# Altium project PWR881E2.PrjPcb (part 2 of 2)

## Sheet PWR881E2.SchDoc: bq2597x and bq25890
size 431 x 279 mm; Date: Not shown in title block; ApprovedBy: Not shown in title block; CheckedBy: Not shown in title block; Author: Not shown in title block; CompanyName: Not shown in title block; Engineer: Not shown in title block; Organization: Not shown in title block; Address1: Not shown in title block; Address2: Not shown in title block; Address3: Not shown in title block; Address4: Not shown in title block; DocumentNumber: 1; Revision: Use project parameter SCH_Rev; SheetNumber: 3; SheetTotal: 4; PageSetup: Record=PageOptions¦CenterHorizontal=True¦CenterVertical=True¦PrintScale=1.00¦XCorrection=1.00¦YCorrection=1.00¦PrintKind=0¦BorderSize=5000000¦LeftOffset=0¦BottomOffset=0¦Orientation=2¦PaperLength=1000¦PaperWidth=1000¦Scale=100¦PaperSource=15¦PrintQuality=600¦MediaType=1¦DitherType=10¦PaperKind=Letter¦PrintScaleMode=1
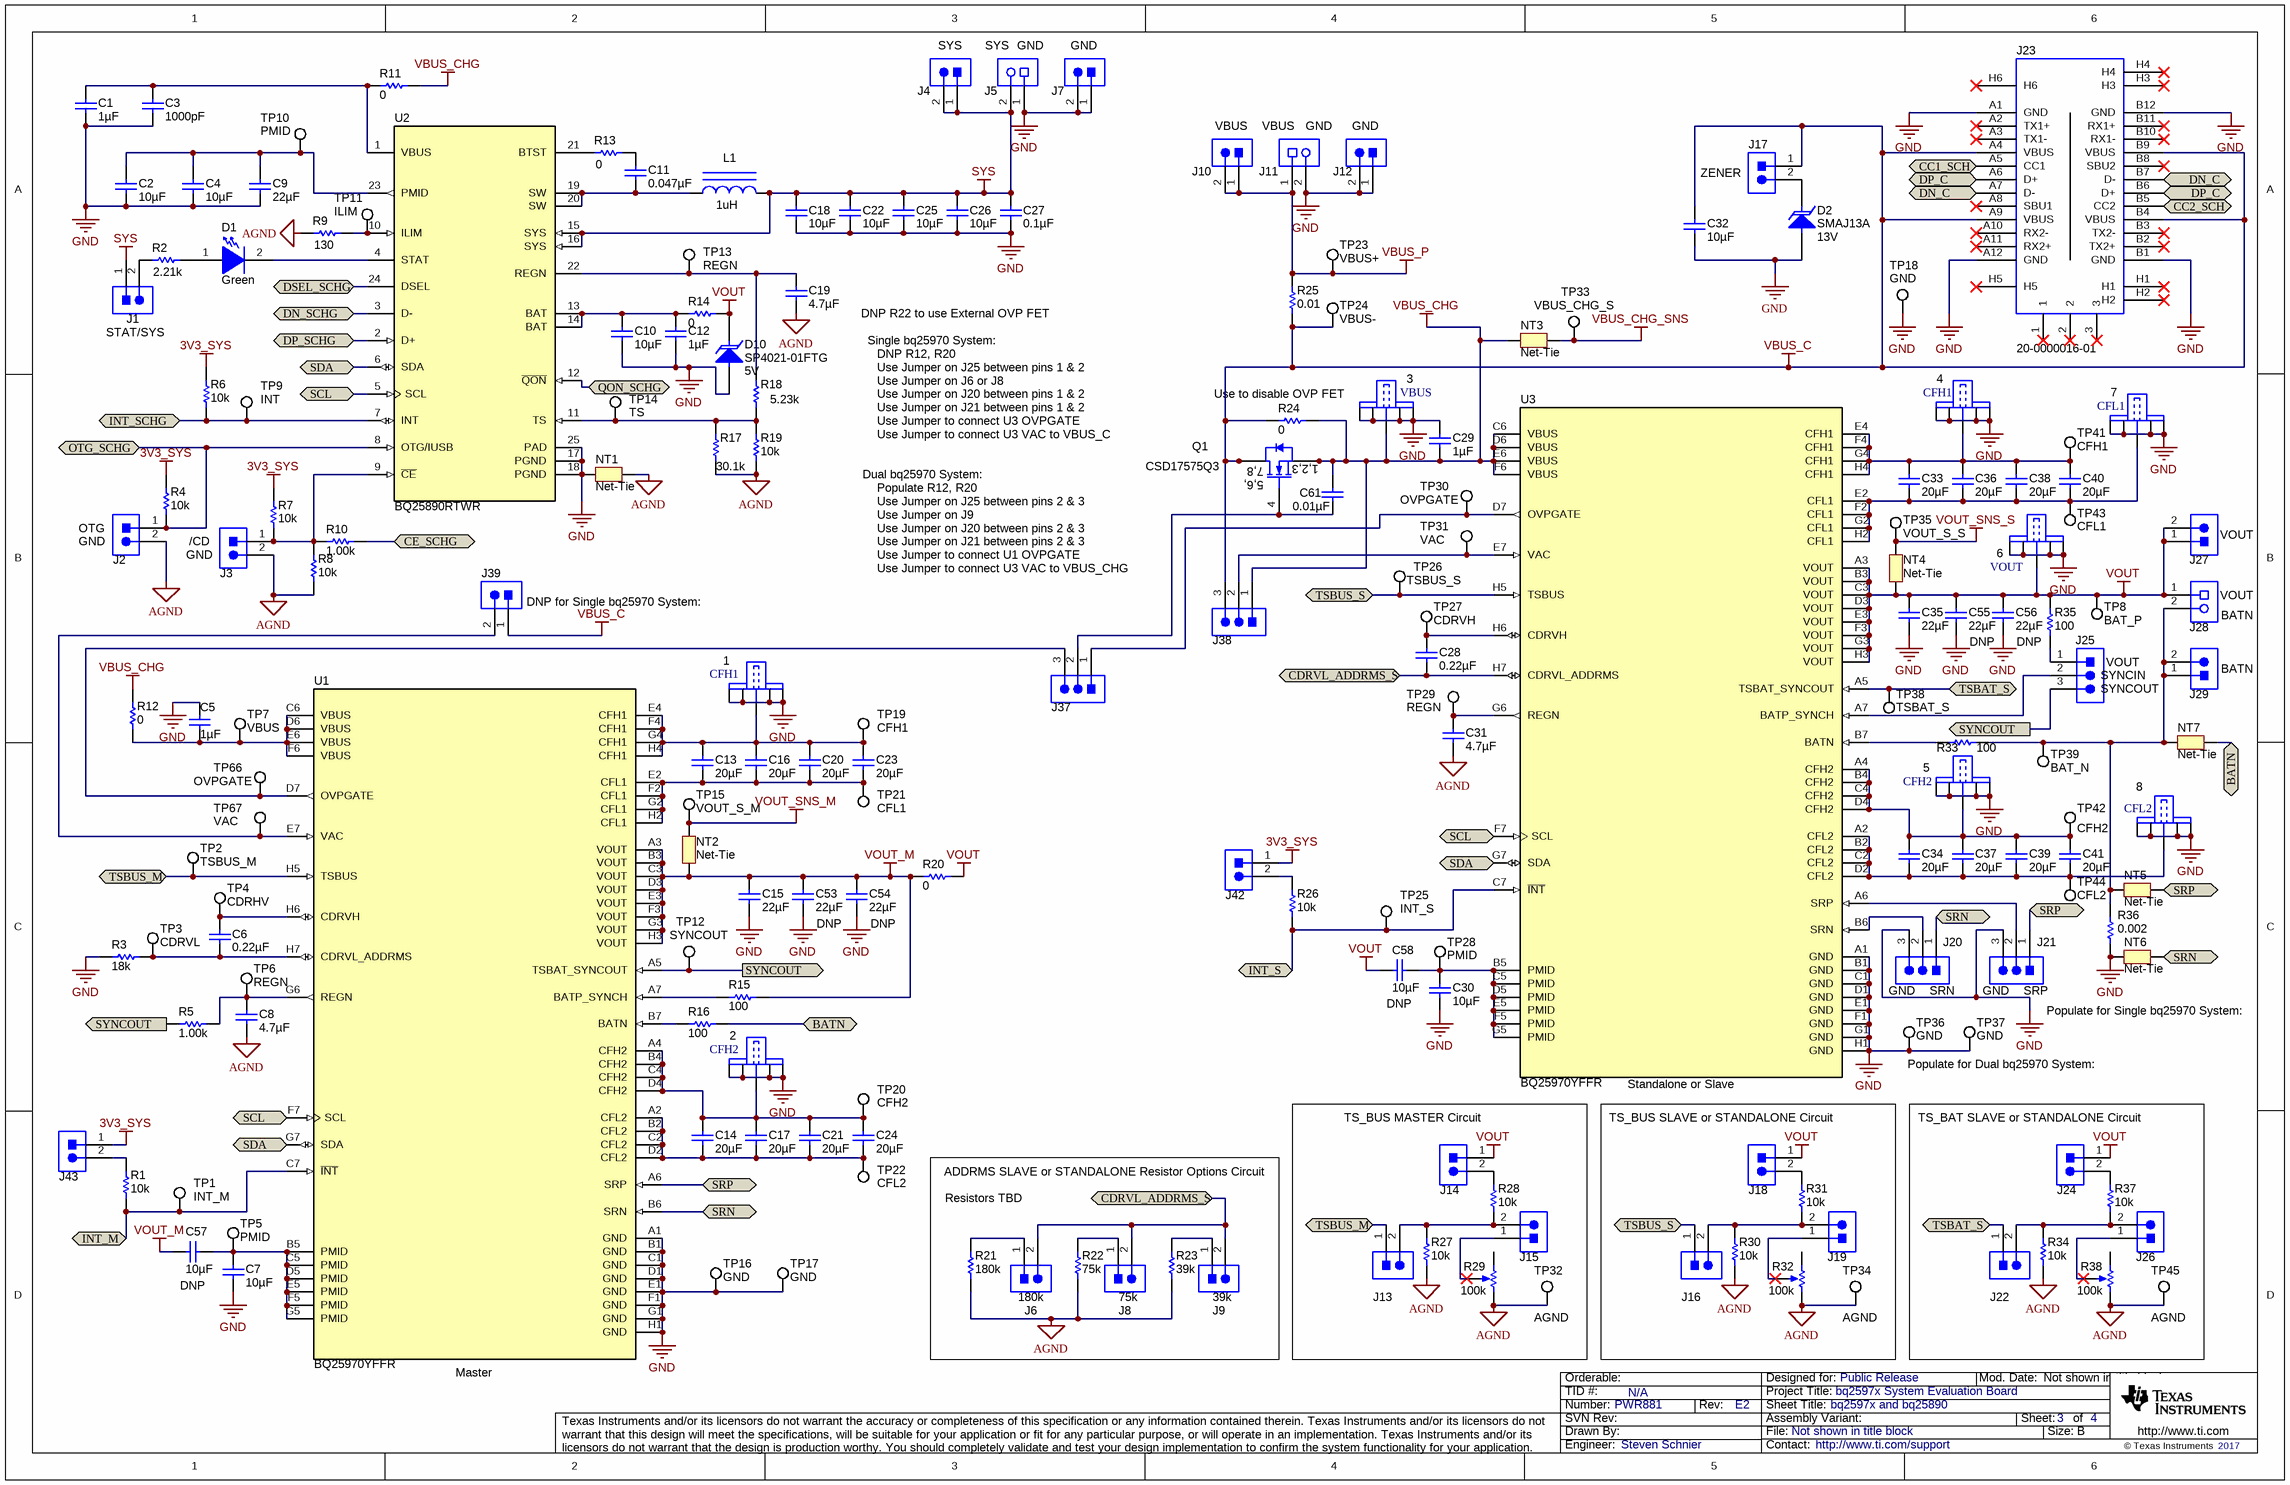
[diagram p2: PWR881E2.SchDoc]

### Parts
1  CFH1  [PROBE]
2  CFH2  [PROBE]
3  VBUS  [PROBE]
4  CFH1  [PROBE]
5  CFH2  [PROBE]
6  VOUT  [PROBE]
7  CFL1  [PROBE]
8  CFL2  [PROBE]
C1  ValueDisplayed: 1µF  [0805_HV]  (hidden comment: GRM219R71E105KA88D)
C2  ValueDisplayed: 10µF  [0603L]  (hidden comment: GRM188R61E106MA73D)
C3  ValueDisplayed: 1000pF  [0603L]  (hidden comment: GRM1885C1E102JA01D)
C4  ValueDisplayed: 10µF  [0603L]  (hidden comment: GRM188R61E106MA73D)
C5  ValueDisplayed: 1µF  [0603L]  (hidden comment: GRM188R61E105KA12D)
C6  ValueDisplayed: 0.22µF  [0402L]  (hidden comment: GRM155R71C224KA12D)
C7  ValueDisplayed: 10µF  [0603L]  (hidden comment: GRM188D71A106MA73D)
C8  ValueDisplayed: 4.7µF  [0402L]  (hidden comment: GRM155R61A475MEAAD)
C9  ValueDisplayed: 22µF  [0805_HV]  (hidden comment: GRM21BR61E226ME44L)
C10  ValueDisplayed: 10µF  [0805L]  (hidden comment: GRM21BR71A106KE51L)
C11  ValueDisplayed: 0.047µF  [0402L]  (hidden comment: GRM155R71E473KA88D)
C12  ValueDisplayed: 1µF  [0603L]  (hidden comment: C1608X7R1C105K080AC)
C13  ValueDisplayed: 20µF  [0704]  (hidden comment: GRMJN7R61C206ME05)
C14  ValueDisplayed: 20µF  [0704]  (hidden comment: GRMJN7R61C206ME05)
C15  ValueDisplayed: 22µF  [0603L]  (hidden comment: GRM188R61A226ME15D)
C16  ValueDisplayed: 20µF  [0704]  (hidden comment: GRMJN7R61C206ME05)
C17  ValueDisplayed: 20µF  [0704]  (hidden comment: GRMJN7R61C206ME05)
C18  ValueDisplayed: 10µF  [0805_HV]  (hidden comment: GRM21BR71A106KE51L)
C19  ValueDisplayed: 4.7µF  [0603L]  (hidden comment: GRM188R61C475KAAJ)
C20  ValueDisplayed: 20µF  [0704]  (hidden comment: GRMJN7R61C206ME05)
C21  ValueDisplayed: 20µF  [0704]  (hidden comment: GRMJN7R61C206ME05)
C22  ValueDisplayed: 10µF  [0805_HV]  (hidden comment: GRM21BR71A106KE51L)
C23  ValueDisplayed: 20µF  [0704]  (hidden comment: GRMJN7R61C206ME05)
C24  ValueDisplayed: 20µF  [0704]  (hidden comment: GRMJN7R61C206ME05)
C25  ValueDisplayed: 10µF  [0805_HV]  (hidden comment: GRM21BR71A106KE51L)
C26  ValueDisplayed: 10µF  [0805_HV]  (hidden comment: GRM21BR71A106KE51L)
C27  ValueDisplayed: 0.1µF  [0603L]  (hidden comment: C1608X7R1E104K080AA)
C28  ValueDisplayed: 0.22µF  [0402L]  (hidden comment: GRM155R71C224KA12D)
C29  ValueDisplayed: 1µF  [0603L]  (hidden comment: GRM188R61E105KA12D)
C30  ValueDisplayed: 10µF  [0603L]  (hidden comment: GRM188D71A106MA73D)
C31  ValueDisplayed: 4.7µF  [0402L]  (hidden comment: GRM155R61A475MEAAD)
C32  ValueDisplayed: 10µF  [0805_HV]  (hidden comment: C2012X5R1E106K125AB)
C33  ValueDisplayed: 20µF  [0704]  (hidden comment: GRMJN7R61C206ME05)
C34  ValueDisplayed: 20µF  [0704]  (hidden comment: GRMJN7R61C206ME05)
C35  ValueDisplayed: 22µF  [0603L]  (hidden comment: GRM188R61A226ME15D)
C36  ValueDisplayed: 20µF  [0704]  (hidden comment: GRMJN7R61C206ME05)
C37  ValueDisplayed: 20µF  [0704]  (hidden comment: GRMJN7R61C206ME05)
C38  ValueDisplayed: 20µF  [0704]  (hidden comment: GRMJN7R61C206ME05)
C39  ValueDisplayed: 20µF  [0704]  (hidden comment: GRMJN7R61C206ME05)
C40  ValueDisplayed: 20µF  [0704]  (hidden comment: GRMJN7R61C206ME05)
C41  ValueDisplayed: 20µF  [0704]  (hidden comment: GRMJN7R61C206ME05)
C53  ValueDisplayed: 22µF  [0603L]  (hidden comment: GRM188R61A226ME15D)
C54  ValueDisplayed: 22µF  [0603L]  (hidden comment: GRM188R61A226ME15D)
C55  ValueDisplayed: 22µF  [0603L]  (hidden comment: GRM188R61A226ME15D)
C56  ValueDisplayed: 22µF  [0603L]  (hidden comment: GRM188R61A226ME15D)
C57  ValueDisplayed: 10µF  [0603L]  (hidden comment: GRM188D71A106MA73D)
C58  ValueDisplayed: 10µF  [0603L]  (hidden comment: GRM188D71A106MA73D)
C61  ValueDisplayed: 0.01µF  [0603L]  (hidden comment: GRM188R71E103KA01D)
D1  value Green  [LED_LTST-C190]  (hidden comment: LTST-C190GKT)
D2  SMAJ13A  value 13V  [SMA]
D10  SP4021-01FTG  value 5V  [SOD-323]
J1  STAT/SYS  [CONN_PEC02SAAN]
J2  PEC02SAAN  [CONN_PEC02SAAN]  (value not drawn)
J3  PEC02SAAN  [CONN_PEC02SAAN]  (value not drawn)
J4  PEC02SAAN  [CONN_PEC02SAAN]  (value not drawn)
J5  1727010  [PhoenixConact_1727010]  (value not drawn)
J6  180k  [CONN_PEC02SAAN]
J7  PEC02SAAN  [CONN_PEC02SAAN]  (value not drawn)
J8  75k  [CONN_PEC02SAAN]
J9  39k  [CONN_PEC02SAAN]
J10  PEC02SAAN  [CONN_PEC02SAAN]  (value not drawn)
J11  1727010  [PhoenixConact_1727010]  (value not drawn)
J12  PEC02SAAN  [CONN_PEC02SAAN]  (value not drawn)
J13  PEC02SAAN  [CONN_PEC02SAAN]  (value not drawn)
J14  PEC02SAAN  [CONN_PEC02SAAN]  (value not drawn)
J15  PEC02SAAN  [CONN_PEC02SAAN]  (value not drawn)
J16  PEC02SAAN  [CONN_PEC02SAAN]  (value not drawn)
J17  PEC02SAAN  [CONN_PEC02SAAN]  (value not drawn)
J18  PEC02SAAN  [CONN_PEC02SAAN]  (value not drawn)
J19  PEC02SAAN  [CONN_PEC02SAAN]  (value not drawn)
J20  TSW-103-07-T-S  [Samtec_TSW-103-07-T-S]  (value not drawn)
J21  TSW-103-07-T-S  [Samtec_TSW-103-07-T-S]  (value not drawn)
J22  PEC02SAAN  [CONN_PEC02SAAN]  (value not drawn)
J23  20-0000016-01  [Lintes_20-0000016-01]
J24  PEC02SAAN  [CONN_PEC02SAAN]  (value not drawn)
J25  TSW-103-07-T-S  [Samtec_TSW-103-07-T-S]  (value not drawn)
J26  PEC02SAAN  [CONN_PEC02SAAN]  (value not drawn)
J27  PEC02SAAN  [CONN_PEC02SAAN]  (value not drawn)
J28  1727010  [PhoenixConact_1727010]  (value not drawn)
J29  PEC02SAAN  [CONN_PEC02SAAN]  (value not drawn)
J37  TSW-103-07-T-S  [Samtec_TSW-103-07-T-S]  (value not drawn)
J38  TSW-103-07-T-S  [Samtec_TSW-103-07-T-S]  (value not drawn)
J39  PEC02SAAN  [CONN_PEC02SAAN]  (value not drawn)
J42  PEC02SAAN  [CONN_PEC02SAAN]  (value not drawn)
J43  PEC02SAAN  [CONN_PEC02SAAN]  (value not drawn)
L1  value 1uH  [IHLP-2020BZ]  (hidden comment: IHLP2020BZER1R0M11)
NT1  Net-Tie  [Net-Tie_10milWide_30milLong]  (net tie, no BOM)
NT2  Net-Tie  [Net-Tie_10milWide_30milLong]  (net tie, no BOM)
NT3  Net-Tie  [Net-Tie_10milWide_30milLong]  (net tie, no BOM)
NT4  Net-Tie  [Net-Tie_10milWide_30milLong]  (net tie, no BOM)
NT5  Net-Tie  [Net-Tie_10milWide_30milLong]  (net tie, no BOM)
NT6  Net-Tie  [Net-Tie_10milWide_30milLong]  (net tie, no BOM)
NT7  Net-Tie  [Net-Tie_10milWide_30milLong]  (net tie, no BOM)
Q1  CSD17575Q3  [DQG0008A]
R1  ValueDisplayed: 10k  [0402L]  (hidden comment: CRCW040210K0JNED)
R2  ValueDisplayed: 2.21k  [0402L]  (hidden comment: CRCW04022K21FKED)
R3  ValueDisplayed: 18k  [0402L]  (hidden comment: CRCW040218K0JNED)
R4  ValueDisplayed: 10k  [0402L]  (hidden comment: CRCW040210K0JNED)
R5  ValueDisplayed: 1.00k  [0603L]  (hidden comment: RC0603FR-071KL)
R6  ValueDisplayed: 10k  [0402L]  (hidden comment: CRCW040210K0JNED)
R7  ValueDisplayed: 10k  [0402L]  (hidden comment: CRCW040210K0JNED)
R8  ValueDisplayed: 10k  [0402L]  (hidden comment: CRCW040210K0JNED)
R9  ValueDisplayed: 130  [0402L]  (hidden comment: CRCW0402130RFKED)
R10  ValueDisplayed: 1.00k  [0603L]  (hidden comment: RC0603FR-071KL)
R11  ValueDisplayed: 0  [2512L]  (hidden comment: CRCW25120000Z0EGHP)
R12  ValueDisplayed: 0  [2512L]  (hidden comment: CRCW25120000Z0EGHP)
R13  ValueDisplayed: 0  [0402L]  (hidden comment: CRCW04020000Z0ED)
R14  ValueDisplayed: 0  [5106]  (hidden comment: 5106)
R15  ValueDisplayed: 100  [0603L]  (hidden comment: CRCW0603100RJNEA)
R16  ValueDisplayed: 100  [0603L]  (hidden comment: CRCW0603100RJNEA)
R17  ValueDisplayed: 30.1k  [0402L]  (hidden comment: CRCW040230K1FKED)
R18  ValueDisplayed: 5.23k  [0402L]  (hidden comment: CRCW04025K23FKED)
R19  ValueDisplayed: 10k  [0402L]  (hidden comment: CRCW040210K0JNED)
R20  ValueDisplayed: 0  [2512L]  (hidden comment: CRCW25120000Z0EGHP)
R21  ValueDisplayed: 180k  [0402]  (hidden comment: CRCW0402180KJNED)
R22  ValueDisplayed: 75k  [0402]  (hidden comment: CRCW040275K0JNED)
R23  ValueDisplayed: 39k  [0402]  (hidden comment: CRCW040239K0JNED)
R24  ValueDisplayed: 0  [2512L]  (hidden comment: CRCW25120000Z0EGHP)
R25  ValueDisplayed: 0.01  [1206]  (hidden comment: WSLP1206R0100FEA)
R26  ValueDisplayed: 10k  [0402L]  (hidden comment: CRCW040210K0JNED)
R27  ValueDisplayed: 10k  [0402]  (hidden comment: CRCW040210K0JNED)
R28  ValueDisplayed: 10k  [0402]  (hidden comment: CRCW040210K0JNED)
R29  value 100k  [TRIM_3266W]  (hidden comment: 3266W-1-104LF)
R30  ValueDisplayed: 10k  [0402]  (hidden comment: CRCW040210K0JNED)
R31  ValueDisplayed: 10k  [0402]  (hidden comment: CRCW040210K0JNED)
R32  value 100k  [TRIM_3266W]  (hidden comment: 3266W-1-104LF)
R33  ValueDisplayed: 100  [0603L]  (hidden comment: CRCW0603100RJNEA)
R34  ValueDisplayed: 10k  [0402]  (hidden comment: CRCW040210K0JNED)
R35  ValueDisplayed: 100  [0603L]  (hidden comment: CRCW0603100RJNEA)
R36  ValueDisplayed: 0.002  [1206]  (hidden comment: CSNL1206FT2L00)
R37  ValueDisplayed: 10k  [0402]  (hidden comment: CRCW040210K0JNED)
R38  value 100k  [TRIM_3266W]  (hidden comment: 3266W-1-104LF)
TP1  INT_M  [Keystone5002]
TP2  TSBUS_M  [Keystone5012]
TP3  CDRVL  [Keystone5012]
TP4  CDRHV  [Keystone5012]
TP5  PMID  [Keystone5012]
TP6  REGN  [Keystone5012]
TP7  VBUS  [Keystone5012]
TP8  BAT_P  [Keystone5012]
TP9  INT  [Keystone5012]
TP10  PMID  [Keystone5012]
TP11  ILIM  [Keystone5012]
TP12  SYNCOUT  [Keystone5012]
TP13  REGN  [Keystone5012]
TP14  TS  [Keystone5012]
TP15  VOUT_S_M  [Keystone5012]
TP16  GND  [Keystone5012]
TP17  GND  [Keystone5012]
TP18  GND  [Keystone5012]
TP19  CFH1  [Keystone5012]
TP20  CFH2  [Keystone5012]
TP21  CFL1  [Keystone5012]
TP22  CFL2  [Keystone5012]
TP23  VBUS+  [Keystone5012]
TP24  VBUS-  [Keystone5012]
TP25  INT_S  [Keystone5002]
TP26  TSBUS_S  [Keystone5012]
TP27  CDRVH  [Keystone5012]
TP28  PMID  [Keystone5012]
TP29  REGN  [Keystone5012]
TP30  OVPGATE  [Keystone5012]
TP31  VAC  [Keystone5012]
TP32  AGND  [Keystone5012]
TP33  VBUS_CHG_S  [Keystone5012]
TP34  AGND  [Keystone5012]
TP35  VOUT_S_S  [Keystone5012]
TP36  GND  [Keystone5012]
TP37  GND  [Keystone5012]
TP38  TSBAT_S  [Keystone5012]
TP39  BAT_N  [Keystone5012]
TP41  CFH1  [Keystone5012]
TP42  CFH2  [Keystone5012]
TP43  CFL1  [Keystone5012]
TP44  CFL2  [Keystone5012]
TP45  AGND  [Keystone5012]
TP66  OVPGATE  [Keystone5012]
TP67  VAC  [Keystone5012]
U1  BQ25970YFFR  [YFF0056ACAJ]
U2  BQ25890RTWR  [RTW0024H]
U3  BQ25970YFFR  [YFF0056ACAJ]

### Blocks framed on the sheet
TS_BUS MASTER Circuit: J13-J15 R27-R29 TP32
TS_BUS SLAVE or STANDALONE Circuit: J16 J18 J19 R30-R32 TP34
TS_BAT SLAVE or STANDALONE Circuit: J22 J24 J26 R34 R37 R38 TP45

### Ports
BATN (bidir), CC1_SCH (bidir), CC2_SCH (bidir), CDRVL_ADDRMS_S (bidir), CE_SCHG (bidir), DN_C (bidir), DN_SCHG (bidir), DP_C (bidir), DP_SCHG (bidir), DSEL_SCHG (bidir), INT_M (bidir), INT_S (bidir), INT_SCHG (bidir), OTG_SCHG (bidir), QON_SCHG (bidir), SCL (bidir), SDA (bidir), SRN (bidir), SRP (bidir), SYNCOUT (out), TSBAT_S (bidir), TSBUS_M (bidir), TSBUS_S (bidir)

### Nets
3V3_SYS: J42.1 J43.1 R4.2 R6.2 R7.2
AGND: C8.2 C19.2 C31.2 J2.2 J3.2 NT1.2 R8.1 R9.2 R17.1 R19.1 R21.1 R22.1 R23.1 R27.1 R29.3(CW) R30.1 R32.3(CW) R34.1 R38.3(CW) TP32.1 TP34.1 TP45.1
GND: 1.2(GND) 1.3(GND) 1.4(GND) 1.5(GND) 2.2(GND) 2.3(GND) 2.4(GND) 2.5(GND) 3.2(GND) 3.3(GND) 3.4(GND) 3.5(GND) 4.2(GND) 4.3(GND) 4.4(GND) 4.5(GND) 5.2(GND) 5.3(GND) 5.4(GND) 5.5(GND) 6.2(GND) 6.3(GND) 6.4(GND) 6.5(GND) 7.2(GND) 7.3(GND) 7.4(GND) 7.5(GND) 8.2(GND) 8.3(GND) 8.4(GND) 8.5(GND) C1.2 C2.2 C3.2 C4.2 C5.1 C7.2 C9.2 C10.2 C12.2 C15.2 C18.2 C22.2 C25.2 C26.2 C27.2 C29.1 C30.2 C32.2 C35.2 C53.2 C54.2 C55.2 C56.2 D2.2(A) D10.2(A) J5.1 J7.1 J7.2 J11.2 J12.1 J12.2 J20.3 J21.3 J23.A1(GND) J23.A12(GND) J23.B1(GND) J23.B12(GND) NT1.1 NT6.1 R3.2 R36.1 TP16.1 TP17.1 TP18.1 TP36.1 TP37.1 U1.A1(GND) U1.B1(GND) U1.C1(GND) U1.D1(GND) U1.E1(GND) U1.F1(GND) U1.G1(GND) U1.H1(GND) U2.17(PGND) U2.18(PGND) U2.25(PAD) U3.A1(GND) U3.B1(GND) U3.C1(GND) U3.D1(GND) U3.E1(GND) U3.F1(GND) U3.G1(GND) U3.H1(GND)
SYS: C18.1 C22.1 C25.1 C26.1 C27.1 J1.1 J4.1 J4.2 J5.2 L1.2 U2.15(SYS) U2.16(SYS)
VBUS_C: C32.1 J17.1 J23.A4(VBUS) J23.A9(VBUS) J23.B4(VBUS) J23.B9(VBUS) J38.3 J39.1 Q1.5(D) Q1.6(D) Q1.7(D) Q1.8(D) Q1.9(D) R24.1 R25.1 TP24.1
VBUS_CHG: 3.1(SIGNAL) C29.2 C61.1 J38.1 NT3.1 Q1.1(S) Q1.2(S) Q1.3(S) R11.2 R12.2 R24.2 U3.C6(VBUS) U3.D6(VBUS) U3.E6(VBUS) U3.F6(VBUS)
VBUS_CHG_SNS: NT3.2 TP33.1
VBUS_P: J10.1 J10.2 J11.1 R25.2 TP23.1
VOUT: 6.1(SIGNAL) C35.1 C55.1 C56.1 C58.1 D10.1(K) J14.1 J18.1 J24.1 J27.1 J27.2 J28.1 NT4.1 R14.2 R20.2 R35.1 TP8.1 U3.A3(VOUT) U3.B3(VOUT) U3.C3(VOUT) U3.D3(VOUT) U3.E3(VOUT) U3.F3(VOUT) U3.G3(VOUT) U3.H3(VOUT)
VOUT_M: C15.1 C53.1 C54.1 C57.1 NT2.1 R15.2 R20.1 U1.A3(VOUT) U1.B3(VOUT) U1.C3(VOUT) U1.D3(VOUT) U1.E3(VOUT) U1.F3(VOUT) U1.G3(VOUT) U1.H3(VOUT)
VOUT_SNS_M: NT2.2 TP15.1
VOUT_SNS_S: NT4.2 TP35.1
BATN: NT7.2 R16.2 ; port BATN
CC1_SCH: J23.A5(CC1) ; port CC1_SCH
CC2_SCH: J23.B5(CC2) ; port CC2_SCH
CDRVL_ADDRMS_S: C28.2 J6.2 J8.2 J9.2 U3.H7(CDRVL_ADDRMS) ; port CDRVL_ADDRMS_S
CE_SCHG: R10.1 ; port CE_SCHG
DN_C: J23.A7(D-) J23.B7(D-) ; port DN_C
DN_SCHG: U2.3(D-) ; port DN_SCHG
DP_C: J23.A6(D+) J23.B6(D+) ; port DP_C
DP_SCHG: U2.2(D+) ; port DP_SCHG
DSEL_SCHG: U2.24(DSEL) ; port DSEL_SCHG
INT_M: R1.1 TP1.1 U1.C7(~{INT}) ; port INT_M
INT_S: R26.1 TP25.1 U3.C7(~{INT}) ; port INT_S
INT_SCHG: R6.1 TP9.1 U2.7(INT) ; port INT_SCHG
OTG_SCHG: J2.1 R4.1 U2.8(OTG/IUSB) ; port OTG_SCHG
QON_SCHG: U2.12(~{QON}) ; port QON_SCHG
SCL: U1.F7(SCL) U2.5(SCL) U3.F7(SCL) ; port SCL
SDA: U1.G7(SDA) U2.6(SDA) U3.G7(SDA) ; port SDA
SRN: J20.1 NT6.2 U1.B6(SRN) ; port SRN
SRP: J21.1 NT5.2 U1.A6(SRP) ; port SRP
SYNCOUT: J25.3 R5.2 TP12.1 U1.A5(TSBAT_SYNCOUT) ; port SYNCOUT
TSBAT_S: J22.1 TP38.1 U3.A5(TSBAT_SYNCOUT) ; port TSBAT_S
TSBUS_M: J13.1 TP2.1 U1.H5(TSBUS) ; port TSBUS_M
TSBUS_S: J16.1 TP26.1 U3.H5(TSBUS) ; port TSBUS_S
Net1_1: 1.1(SIGNAL) C13.1 C16.1 C20.1 C23.1 TP19.1 U1.E4(CFH1) U1.F4(CFH1) U1.G4(CFH1) U1.H4(CFH1)
Net2_1: 2.1(SIGNAL) C14.1 C17.1 C21.1 C24.1 TP20.1 U1.A4(CFH2) U1.B4(CFH2) U1.C4(CFH2) U1.D4(CFH2)
Net4_1: 4.1(SIGNAL) C33.1 C36.1 C38.1 C40.1 TP41.1 U3.E4(CFH1) U3.F4(CFH1) U3.G4(CFH1) U3.H4(CFH1)
Net5_1: 5.1(SIGNAL) C34.1 C37.1 C39.1 C41.1 TP42.1 U3.A4(CFH2) U3.B4(CFH2) U3.C4(CFH2) U3.D4(CFH2)
Net7_1: 7.1(SIGNAL) C33.2 C36.2 C38.2 C40.2 TP43.1 U3.E2(CFL1) U3.F2(CFL1) U3.G2(CFL1) U3.H2(CFL1)
Net8_1: 8.1(SIGNAL) C34.2 C37.2 C39.2 C41.2 TP44.1 U3.A2(CFL2) U3.B2(CFL2) U3.C2(CFL2) U3.D2(CFL2)
NetC1_1: C1.1 C3.1 R11.1 U2.1(VBUS)
NetC2_1: C2.1 C4.1 C9.1 TP10.1 U2.23(PMID)
NetC5_2: C5.2 R12.1 TP7.1 U1.C6(VBUS) U1.D6(VBUS) U1.E6(VBUS) U1.F6(VBUS)
NetC6_1: C6.1 TP4.1 U1.H6(CDRVH)
NetC6_2: C6.2 R3.1 TP3.1 U1.H7(CDRVL_ADDRMS)
NetC7_1: C7.1 C57.2 TP5.1 U1.B5(PMID) U1.C5(PMID) U1.D5(PMID) U1.E5(PMID) U1.F5(PMID) U1.G5(PMID)
NetC8_1: C8.1 R5.1 TP6.1 U1.G6(REGN)
NetC10_1: C10.1 C12.1 R14.1 U2.13(BAT) U2.14(BAT)
NetC11_1: C11.1 R13.1
NetC11_2: C11.2 L1.1 U2.19(SW) U2.20(SW)
NetC13_2: C13.2 C16.2 C20.2 C23.2 TP21.1 U1.E2(CFL1) U1.F2(CFL1) U1.G2(CFL1) U1.H2(CFL1)
NetC14_2: C14.2 C17.2 C21.2 C24.2 TP22.1 U1.A2(CFL2) U1.B2(CFL2) U1.C2(CFL2) U1.D2(CFL2)
NetC19_1: C19.1 R18.1 TP13.1 U2.22(REGN)
NetC28_1: C28.1 TP27.1 U3.H6(CDRVH)
NetC30_1: C30.1 C58.2 TP28.1 U3.B5(PMID) U3.C5(PMID) U3.D5(PMID) U3.E5(PMID) U3.F5(PMID) U3.G5(PMID)
NetC31_1: C31.1 TP29.1 U3.G6(REGN)
NetC61_2: C61.2 J37.2 Q1.4(G)
NetD1_1: D1.1(A) R2.1
NetD1_2: D1.2(K) U2.4(STAT)
NetD2_1: D2.1(K) J17.2
NetJ1_2: J1.2 R2.2
NetJ3_1: J3.1 R7.1 R8.2 R10.2 U2.9(~{CE})
NetJ6_1: J6.1 R21.2
NetJ8_1: J8.1 R22.2
NetJ9_1: J9.1 R23.2
NetJ13_2: J13.2 J15.2 R27.2 R28.1
NetJ14_2: J14.2 R28.2
NetJ15_1: J15.1 R29.2(WIPER)
NetJ16_2: J16.2 J19.2 R30.2 R31.1
NetJ18_2: J18.2 R31.2
NetJ19_1: J19.1 R32.2(WIPER)
NetJ20_2: J20.2 U3.B6(SRN)
NetJ21_2: J21.2 U3.A6(SRP)
NetJ22_2: J22.2 J26.2 R34.2 R37.1
NetJ24_2: J24.2 R37.2
NetJ25_1: J25.1 R35.2
NetJ25_2: J25.2 U3.A7(BATP_SYNCH)
NetJ26_1: J26.1 R38.2(WIPER)
NetJ28_2: J28.2 J29.1 J29.2 NT5.1 NT7.1 R33.2 R36.2 TP39.1
NetJ37_1: J37.1 TP30.1 U3.D7(OVPGATE)
NetJ37_3: J37.3 TP66.1 U1.D7(OVPGATE)
NetJ38_2: J38.2 TP31.1 U3.E7(VAC)
NetJ39_2: J39.2 TP67.1 U1.E7(VAC)
NetJ42_2: J42.2 R26.2
NetJ43_2: J43.2 R1.2
NetR9_1: R9.1 TP11.1 U2.10(ILIM)
NetR13_2: R13.2 U2.21(BTST)
NetR15_1: R15.1 U1.A7(BATP_SYNCH)
NetR16_1: R16.1 U1.B7(BATN)
NetR17_2: R17.2 R18.2 R19.2 TP14.1 U2.11(TS)
NetR33_1: R33.1 U3.B7(BATN)

Not connected (* = marked no-connect by the designer): J23 1* 2* 3* A2(TX1+)* A3(TX1-)* A8(SBU1)* A10(RX2-)* A11(RX2+)* B2(TX2+)* B3(TX2-)* B8(SBU2)* B10(RX1-)* B11(RX1+)* H1* H2* H3* H4* H5* H6*; R29 1(CCW); R32 1(CCW); R38 1(CCW)

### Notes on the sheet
- (near J4) SYS
- SYS
- GND
- (near J7) GND
- (near J10) VBUS
- VBUS
- (near J12) GND
- ZENER
- DNP R12, R20
- Use Jumper on J25 between pins 1 & 2
- Single bq25970 System:
- DNP R22 to use External OVP FET
- Use Jumper on J6 or J8
- Use Jumper on J20 between pins 1 & 2
- Use Jumper on J21 between pins 1 & 2
- Use Jumper to connect U3 OVPGATE
- Use Jumper to connect U3 VAC to VBUS_C
- Use to disable OVP FET
- Populate R12, R20
- Use Jumper on J25 between pins 2 & 3
- Dual bq25970 System:
- (near J2) OTG
- (near J2) GND
- /CD
- Use Jumper on J9
- Use Jumper on J20 between pins 2 & 3
- Use Jumper on J21 between pins 2 & 3
- Use Jumper to connect U1 OVPGATE
- Use Jumper to connect U3 VAC to VBUS_CHG
- (near J27) VOUT
- (near J39) DNP for Single bq25970 System:
- BATN
- (near J28) VOUT
- DNP
- (near R35) DNP
- VOUT
- (near J25) SYNCIN
- SYNCOUT
- (near J29) BATN
- (near C54) DNP
- SRN
- (near J21) SRP
- Populate for Single bq25970 System:
- (near U3) Standalone or Slave
- Populate for Dual bq25970 System:
- ADDRMS SLAVE or STANDALONE Resistor Options Circuit
- Resistors TBD
- (near U1) Master

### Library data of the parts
1-8 = TP_PROBE: Adaptor, 3.5-mm probe clip (or 131-5031-00); Manufacturer: Tektronix; PartNumber: 131-4244-00; Value: 131-4244-00
C1 = GRM219R71E105KA88D: CAP, CERM, 1 µF, 25 V, +/- 10%, X7R, 0805; Manufacturer: MuRata; Polarized: N; CompType: Capacitor; Value: 1uF; U/M: EA; Cap_F: 0.000001; Tolerance_%: 10; Value1: Unknown; VDC_V: 25; Value2: 25V; TaMin_C: -55; TaMax_C: 125; Cap_Case: 0805; SizeArea_mm2: 2.5; SizeAreaWB_mm2: 6.75; SizeX_mm: 2; SizeY_mm: 1.25; SizeZ_mm: 1.45; AEC Category: Q200
C2 C4 = GRM188R61E106MA73D: CAP, CERM, 10 µF, 25 V, +/- 20%, X5R, 0603; Manufacturer: MuRata; Polarized: N; CompType: Capacitor; Value: 10uF; U/M: EA; Cap_F: 0.00001; Tolerance_%: 20; Value1: Unknown; VDC_V: 25; Value2: 25V; TaMin_C: -55; TaMax_C: 85; Cap_Case: 0603; SizeArea_mm2: 1.28; SizeAreaWB_mm2: 4.68; SizeX_mm: 1.6; SizeY_mm: 0.8; SizeZ_mm: 1; AEC Category: Q200
C3 = GRM1885C1E102JA01D: CAP, CERM, 1000 pF, 25 V, +/- 5%, C0G/NP0, 0603; Manufacturer: MuRata; Polarized: N; CompType: Capacitor; Value: 1000pF; U/M: EA; Cap_F: 0.000000001; Tolerance_%: 5; Value1: Unknown; VDC_V: 25; Value2: 25V; TaMin_C: -55; TaMax_C: 125; Cap_Case: 0603; SizeArea_mm2: 1.28; SizeAreaWB_mm2: 4.68; SizeX_mm: 1.6; SizeY_mm: 0.8; SizeZ_mm: 1; AEC Category: Q200
C5 C29 = GRM188R61E105KA12D: CAP, CERM, 1 µF, 25 V, +/- 10%, X5R, 0603; Manufacturer: MuRata; Polarized: N; CompType: Capacitor; Value: 1uF; U/M: EA; Cap_F: 0.000001; Tolerance_%: 10; Value1: Unknown; VDC_V: 25; Value2: 25V; TaMin_C: -55; TaMax_C: 85; Cap_Case: 0603; SizeArea_mm2: 1.28; SizeAreaWB_mm2: 4.68; SizeX_mm: 1.6; SizeY_mm: 0.8; SizeZ_mm: 1; AEC Category: Q200
C6 C28 = GRM155R71C224KA12D: CAP, CERM, 0.22 µF, 16 V, +/- 10%, X7R, 0402; Manufacturer: MuRata; Polarized: N; CompType: Capacitor; Value: 0.22uF; U/M: EA; Cap_F: 0.00000022; Tolerance_%: 10; Value1: Unknown; VDC_V: 16; Value2: 16V; TaMin_C: -55; TaMax_C: 125; Cap_Case: 0402; SizeArea_mm2: 0.5; SizeAreaWB_mm2: 3; SizeX_mm: 1; SizeZ_mm: 0.6; AEC Category: Q200
C7 C30 C57 C58 = GRM188D71A106MA73D: CAP, CERM, 10 µF, 10 V, +/- 20%, X7T, 0603; Manufacturer: MuRata; Polarized: N; CompType: Capacitor; Value: 10uF; U/M: EA; Cap_F: 0.00001; Tolerance_%: 20; Value1: Unknown; VDC_V: 10; Value2: 10V; TaMin_C: -55; TaMax_C: 125; Cap_Case: 0603; SizeArea_mm2: 1.28; SizeAreaWB_mm2: 4.68; SizeX_mm: 1.6; SizeY_mm: 0.8; SizeZ_mm: 1; AEC Category: Q200
C8 C31 = GRM155R61A475MEAAD: CAP, CERM, 4.7 µF, 10 V, +/- 20%, X5R, 0402; Manufacturer: MuRata; Polarized: N; CompType: Capacitor; Value: 4.7uF; U/M: EA; Cap_F: 0.0000047; Tolerance_%: 20; Value1: Unknown; VDC_V: 10; Value2: 10V; TaMin_C: -55; TaMax_C: 85; Cap_Case: 0402; SizeArea_mm2: 0.5; SizeAreaWB_mm2: 3; SizeX_mm: 1; SizeZ_mm: 0.6; AEC Category: Q200
C9 = GRM21BR61E226ME44L: CAP, CERM, 22 µF, 25 V, +/- 20%, X5R, 0805; Manufacturer: MuRata; Polarized: N; CompType: Capacitor; Value: 22uF; U/M: EA; Cap_F: 0.000022; Tolerance_%: 20; Value1: Unknown; VDC_V: 25; Value2: 25V; TaMin_C: -55; TaMax_C: 85; Cap_Case: 0805; SizeArea_mm2: 2.5; SizeAreaWB_mm2: 6.75; SizeX_mm: 2; SizeY_mm: 1.25; SizeZ_mm: 1.45; AEC Category: Q200
C10 C18 C22 C25 C26 = GRM21BR71A106KE51L: CAP, CERM, 10 µF, 10 V, +/- 10%, X7R, 0805; Manufacturer: MuRata; Polarized: N; CompType: Capacitor; Value: 10uF; U/M: EA; Cap_F: 0.00001; Tolerance_%: 10; ESR_ohm: 0.003; Value1: 0.003 ohm; Value2: 10V; TaMin_C: -55; TaMax_C: 125; Cap_Case: 0805; SizeArea_mm2: 2.5; SizeAreaWB_mm2: 6.75; SizeX_mm: 2; SizeY_mm: 1.25; SizeZ_mm: 1.45; AEC Category: Q200
C11 = GRM155R71E473KA88D: CAP, CERM, 0.047 µF, 25 V, +/- 10%, X7R, 0402; Manufacturer: MuRata; Polarized: N; CompType: Capacitor; Value: 0.047uF; U/M: EA; Cap_F: 0.000000047; Tolerance_%: 10; Value1: Unknown; VDC_V: 25; Value2: 25V; TaMin_C: -55; TaMax_C: 125; Cap_Case: 0402; SizeArea_mm2: 0.5; SizeAreaWB_mm2: 3; SizeX_mm: 1; SizeZ_mm: 0.6; AEC Category: Q200
C12 = C1608X7R1C105K080AC: CAP, CERM, 1 µF, 16 V, +/- 10%, X7R, 0603; Manufacturer: TDK; Polarized: N; CompType: Capacitor; Value: 1uF; U/M: EA; Cap_F: 0.000001; Tolerance_%: 10; ESR_ohm: 0.0057; Value1: 0.0057 ohm; VDC_V: 16; Value2: 16V; TaMin_C: -55; TaMax_C: 125; Cap_Case: 0603; SizeArea_mm2: 1.28; SizeAreaWB_mm2: 4.68; SizeX_mm: 1.6; SizeY_mm: 0.8; SizeZ_mm: 1; AEC Category: Q200
C13 C14 C16 C17 C20 C21 C23 C24 C33 C34 C36-C41 = GRMJN7R61C206ME05: CAP, CERM, 20 µF, 16 V, +/- 20%, X5R, 0704; Manufacturer: MuRata; Polarized: N; CompType: Capacitor; Value: 20uF; U/M: EA; Cap_F: 2e-005; Tolerance_%: 20; Value1: Unknown; VDC_V: 16; Value2: 16V; TaMin_C: -55; TaMax_C: 85; SizeArea_mm2: 1.8; SizeAreaWB_mm2: 5.6; SizeX_mm: 1; SizeZ_mm: 0.8; AEC Category: Q200
C15 C35 C53-C56 = GRM188R61A226ME15D: CAP, CERM, 22 µF, 10 V, +/- 20%, X5R, 0603; Manufacturer: MuRata; Polarized: N; CompType: Capacitor; Value: 22uF; U/M: EA; Cap_F: 0.000022; Tolerance_%: 20; Value1: Unknown; VDC_V: 10; Value2: 10V; TaMin_C: -55; TaMax_C: 85; Cap_Case: 0603; SizeArea_mm2: 1.28; SizeAreaWB_mm2: 4.68; SizeX_mm: 1.6; SizeY_mm: 0.8; SizeZ_mm: 1; AEC Category: Q200
C19 = GRM188R61C475KAAJ: CAP, CERM, 4.7 µF, 16 V, +/- 10%, X5R, 0603; Manufacturer: MuRata; Polarized: N; CompType: Capacitor; Value: 4.7uF; U/M: EA; Cap_F: 0.0000047; Tolerance_%: 10; Value1: Unknown; VDC_V: 16; Value2: 16V; TaMin_C: -55; TaMax_C: 85; Cap_Case: 0603; SizeArea_mm2: 1.28; SizeAreaWB_mm2: 4.68; SizeX_mm: 1.6; SizeY_mm: 0.8; SizeZ_mm: 1; AEC Category: Q200
C27 = C1608X7R1E104K080AA: CAP, CERM, 0.1 µF, 25 V, +/- 10%, X7R, 0603; Manufacturer: TDK; Polarized: N; CompType: Capacitor; Value: 0.1uF; U/M: EA; Cap_F: 0.0000001; Tolerance_%: 10; Value1: Unknown; VDC_V: 25; Value2: 25V; TaMin_C: -55; TaMax_C: 125; Cap_Case: 0603; SizeArea_mm2: 1.28; SizeAreaWB_mm2: 4.68; SizeX_mm: 1.6; SizeY_mm: 0.8; SizeZ_mm: 1; AEC Category: Q200
C32 = C2012X5R1E106K125AB: CAP, CERM, 10 µF, 25 V, +/- 10%, X5R, 0805; Manufacturer: TDK; Polarized: N; CompType: Capacitor; Value: 10uF; U/M: EA; Cap_F: 0.00001; Tolerance_%: 10; Value1: Unknown; VDC_V: 25; Value2: 25V; TaMin_C: -55; TaMax_C: 85; Cap_Case: 0805; AEC Category: Q200; SizeArea_mm2: 2.5; SizeAreaWB_mm2: 6.75; SizeX_mm: 2; SizeY_mm: 1.25; SizeZ_mm: 1.45
C61 = GRM188R71E103KA01D: CAP, CERM, 0.01 µF, 25 V,+/- 10%, X7R, 0603; Manufacturer: MuRata; Polarized: N; CompType: Capacitor; Value: 0.01uF; U/M: EA; Cap_F: 0.00000001; Tolerance_%: 10; VDC_V: 25; Value2: 25V; TaMin_C: -55; TaMax_C: 125; Cap_Case: 0603; SizeArea_mm2: 1.28; SizeAreaWB_mm2: 4.68; SizeX_mm: 1.6; SizeY_mm: 0.8; SizeZ_mm: 1; AEC Category: Q200; Green_Lifecycle: Active; Green_REACh: Passed
D1 = LTST-C190GKT: LED, Green, SMD; Manufacturer: Lite-On; Vf_V: 2.1; Value2: 2.1V; Io_A: 0.02; Power_TotalModule: 0.1; Value1: 0.1W; U/M: EA
D2 = SMAJ13A: Diode, TVS, Uni, 13 V, SMA; Manufacturer: Littelfuse; U/M: EA; Power_W: 3.3; Vr_V: 13; Value1: 3.3W; RJA_CperW: 120; AEC Category: Q101; SizeAreaWB_mm2: 37.3428; SizeArea_mm2: 16.3228; SizeX_mm: 5.59; SizeY_mm: 2.92; SizeZ_mm: 2.87
D10 = SP4021-01FTG: Diode, TVS, Uni, 5 V, 19.6 Vc, SOD-323; Manufacturer: Littelfuse; U/M: EA; Vr_V: 5; Value1: W; SizeAreaWB_mm2: 8.695; SizeArea_mm2: 3.645; SizeX_mm: 2.7; SizeY_mm: 1.35; SizeZ_mm: 1; AEC Category: Q101; AEC Qualified: N
J1-J4 J6-J10 J12-J19 J22 J24 J26 J27 J29 J39 J42 J43 = PEC02SAAN: Header, 100mil, 2x1, Tin, TH; Manufacturer: Sullins Connector Solutions; SymbolCreator: a0412235; Pitch_mm: 2.54; Gender: Male; Shrouded: N; Row_Count: 1; Current_A: 3; Voltage_V: 1800; Cert_UL: Y
J5 J11 J28 = 1727010: Conn Term Block, 2POS, 3.81mm, TH; Manufacturer: Phoenix Contact; SymbolCreator: a0412235; CompType: Terminal Block
J20 J21 J25 J37 J38 = TSW-103-07-T-S: Header, 2.54 mm, 3x1, Tin, TH; Manufacturer: Samtec; SymbolCreator: a0799628; Pitch_mm: 2.54; Gender: Male; Shrouded: N; Row_Count: 1; Current_A: 6.3; Voltage_V: 550; Cert_CSA: Y
J23 = 20-0000016-01: Connector, Receptacle, USB Type C, R/A, SMT; Manufacturer: Lintes Technology; SymbolCreator: Altium
L1 = IHLP2020BZER1R0M11: Inductor, Shielded Drum Core, Powdered Iron, 1 µH, 7 A, 0.0181 ohm, SMD; Manufacturer: Vishay-Dale; Ind_H: 1.0E-6; ValueDisplayed: 1µH; Imax_A: 7; Irms: 7.5A @ 40C rise; Isat: 7A @ 20% inductance drop; DCR_ohm: 0.0181; Value2: 7A; SizeAreaWB_mm2: 53.7782; SizeArea_mm2: 28.4382; SizeX_mm: 5.49; SizeY_mm: 5.18; SizeZ_mm: 2; AEC Category: Q200
NT1-NT7 = Net-Tie: Single point connection between nets.; SymbolCreator: codlsc
Q1 = CSD17575Q3: MOSFET, N-CH, 30 V, 60 A, DQG0008A (VSON-CLIP-8); Manufacturer: Texas Instruments; Alternate Manufacturer: None; U/M: EA; ChType: N; Value: 30V; VdsMax_V: 30; Value1: 0.0032 ohm; Rdson45_ohm: 0.0032; Value2: 23 nC; QgTyp_nC: 23; Vgs_V: 20; IdsMax_A: 60; SizeAreaWB_mm2: 18.49; SizeArea_mm2: 10.89; SizeX_mm: 3.3; SizeZ_mm: 1.1; AEC Category: Q101
R1 R4 R6-R8 R19 R26-R28 R30 R31 R34 R37 = CRCW040210K0JNED: RES, 10 k, 5%, 0.063 W, 0402; Manufacturer: Vishay-Dale; CompType: Resistor; Value: 10k; Res_ohm: 10000; Value_Code: 10k0; Tolerance_%: 5; Power_W: 0.063; Value2: 0.063W; VDC_V: 50; TempCo: 200 ppm/C; SizeArea_mm2: 0.5; SizeX_mm: 1; SizeZ_mm: 0.6; EIA_Code: E24; U/M: EA; AEC Category: Q200
R2 = CRCW04022K21FKED: RES, 2.21 k, 1%, 0.063 W, 0402; Manufacturer: Vishay-Dale; CompType: Resistor; Value: 2.21k; Res_ohm: 2210; Value_Code: 2k21; Tolerance_%: 1; Power_W: 0.063; Value2: 0.063W; VDC_V: 50; TempCo: 100 ppm/C; EIA_Code: E96; U/M: EA; SizeArea_mm2: 0.5; SizeZ_mm: 0.6; AEC Category: Q200
R3 = CRCW040218K0JNED: RES, 18 k, 5%, 0.063 W, 0402; Manufacturer: Vishay-Dale; CompType: Resistor; Value: 18k; Res_ohm: 18000; Value_Code: 18k0; Tolerance_%: 5; Power_W: 0.063; Value2: 0.063W; VDC_V: 50; TempCo: 200 ppm/C; SizeArea_mm2: 0.5; SizeX_mm: 1; SizeZ_mm: 0.6; EIA_Code: E24; U/M: EA; AEC Category: Q200
R5 R10 = RC0603FR-071KL: RES, 1.00 k, 1%, 0.1 W, 0603; Manufacturer: Yageo America; CompType: Resistor; Value: 1.00k; Res_ohm: 1000; Value_Code: 1k00; Tolerance_%: 1; Power_W: 0.1; Value2: 0.1W; VDC_V: 150; TempCo: 200 ppm/C; EIA_Code: E96; U/M: EA; AEC Category: Q200; SizeArea_mm2: 1.28; SizeX_mm: 1.6; SizeY_mm: 0.8
R9 = CRCW0402130RFKED: RES, 130, 1%, 0.063 W, 0402; Manufacturer: Vishay-Dale; CompType: Resistor; Value: 130; Value_Code: 130R; Tolerance_%: 1; Power_W: 0.063; Value2: 0.063W; VDC_V: 50; TempCo: 100 ppm/C; EIA_Code: E96; U/M: EA; SizeArea_mm2: 0.5; SizeZ_mm: 0.6; AEC Category: Q200
R11 R12 R20 R24 = CRCW25120000Z0EGHP: RES, 0, 5%, 1.5 W, AEC-Q200 Grade 0, 2512; Manufacturer: Vishay-Dale; CompType: Resistor; Value: 0; Value_Code: 0000; Tolerance_%: 5; Power_W: 1.5; Value2: 1.5W; TempCo: ppm/C; SizeArea_mm2: 20.16; SizeX_mm: 6.3; SizeY_mm: 3.2; SizeZ_mm: 0.71; EIA_Code: E24; U/M: EA; AEC Category: Q200; AEC Qualified: Y
R13 = CRCW04020000Z0ED: RES, 0, 5%, 0.063 W, 0402; Manufacturer: Vishay-Dale; CompType: Resistor; Value: 0; Value_Code: 0000; Tolerance_%: 5; Power_W: 0.063; Value2: 0.063W; VDC_V: 50; TempCo: 200 ppm/C; EIA_Code: E24; U/M: EA; SizeArea_mm2: 0.5; SizeX_mm: 1; SizeZ_mm: 0.6; AEC Category: Q200
R14 = 5106: RES, 0, 1%, 0.5 W, 0805; Manufacturer: Keystone; CompType: Resistor; Value: 0; Tolerance_%: 1; Power_W: 0.5; Value2: 0.5W; TempCo: ppm/C; SizeArea_mm2: 2.5; SizeX_mm: 2; SizeY_mm: 1.25; SizeZ_mm: 0.84; U/M: EA; AEC Category: Q200; AEC Qualified: N
R15 R16 R33 R35 = CRCW0603100RJNEA: RES, 100, 5%, 0.1 W, 0603; Manufacturer: Vishay-Dale; CompType: Resistor; Value: 100; Value_Code: 100R; Tolerance_%: 5; Power_W: 0.1; Value2: 0.1W; VDC_V: 75; TempCo: 200 ppm/C; EIA_Code: E24; U/M: EA; AEC Category: Q200; SizeArea_mm2: 1.28; SizeX_mm: 1.6; SizeY_mm: 0.8; SizeZ_mm: 1
R17 = CRCW040230K1FKED: RES, 30.1 k, 1%, 0.063 W, 0402; Manufacturer: Vishay-Dale; CompType: Resistor; Value: 30.1k; Res_ohm: 30100; Value_Code: 30k1; Tolerance_%: 1; Power_W: 0.063; Value2: 0.063W; VDC_V: 50; TempCo: 100 ppm/C; EIA_Code: E96; U/M: EA; SizeArea_mm2: 0.5; SizeZ_mm: 0.6; AEC Category: Q200
R18 = CRCW04025K23FKED: RES, 5.23 k, 1%, 0.063 W, 0402; Manufacturer: Vishay-Dale; CompType: Resistor; Value: 5.23k; Res_ohm: 5230; Value_Code: 5k23; Tolerance_%: 1; Power_W: 0.063; Value2: 0.063W; VDC_V: 50; TempCo: 100 ppm/C; EIA_Code: E96; U/M: EA; SizeArea_mm2: 0.5; SizeZ_mm: 0.6; AEC Category: Q200
R21 = CRCW0402180KJNED: RES, 180 k, 5%, 0.063 W, 0402; Manufacturer: Vishay-Dale; CompType: Resistor; Value: 180k; Res_ohm: 180000; Tolerance_%: 5; Power_W: 0.063; Value2: 0.063W; VDC_V: 50; TempCo: 200 ppm/C; SizeArea_mm2: 0.5; SizeX_mm: 1; SizeZ_mm: 0.6; EIA_Code: E24; U/M: EA; AEC Category: Q200
R22 = CRCW040275K0JNED: RES, 75 k, 5%, 0.063 W, 0402; Manufacturer: Vishay-Dale; CompType: Resistor; Value: 75k; Res_ohm: 75000; Value_Code: 75k0; Tolerance_%: 5; Power_W: 0.063; Value2: 0.063W; VDC_V: 50; TempCo: 200 ppm/C; SizeArea_mm2: 0.5; SizeX_mm: 1; SizeZ_mm: 0.6; EIA_Code: E24; U/M: EA; AEC Category: Q200
R23 = CRCW040239K0JNED: RES, 39 k, 5%, 0.063 W, 0402; Manufacturer: Vishay-Dale; CompType: Resistor; Value: 39k; Res_ohm: 39000; Value_Code: 39k0; Tolerance_%: 5; Power_W: 0.063; Value2: 0.063W; VDC_V: 50; TempCo: 200 ppm/C; SizeArea_mm2: 0.5; SizeX_mm: 1; SizeZ_mm: 0.6; EIA_Code: E24; U/M: EA; AEC Category: Q200
R25 = WSLP1206R0100FEA: RES, 0.01, 1%, 1 W, 1206; Manufacturer: Vishay-Dale; CompType: Resistor; Value: 0.01; Value_Code: R010; Tolerance_%: 1; Value2: 1W; TempCo: 75 ppm/C; EIA_Code: E96; U/M: EA; AEC Category: Q200; SizeArea_mm2: 5.12; SizeX_mm: 3.2; SizeY_mm: 1.6; SizeZ_mm: 1.35; Green_Lifecycle: Not Set; Green_REACh: Incomplete
R29 R32 R38 = 3266W-1-104LF: Trimmer, 100k ohm, 0.25W, TH; Manufacturer: Bourns; Sim Note: Enter the Resistance value and the set point into parameter fields.; SymbolCreator: a0412235
R36 = CSNL1206FT2L00: RES, 0.002, 1%, 1 W, 1206; Manufacturer: Stackpole Electronics Inc; CompType: Resistor; Value: 0.002; Value_Code: 2L000; Tolerance_%: 1; Value2: 1W; TempCo: 50 ppm/C; U/M: EA; AEC Category: Q200; SizeArea_mm2: 5.12; SizeX_mm: 3.2; SizeY_mm: 1.6; SizeZ_mm: 1.35
TP1-TP39 TP41-TP45 TP66 TP67 = 5012: Test Point, Multipurpose, White, TH; Manufacturer: Keystone; CompType: Test Point Loop; ContactFinish: Silver
U1 U3 = CMP-0075378-1: 97% Efficient, 8A Switched Cap Battery Charger with Integrated Protection, I2C Programmability and ADC, YFF0056ACAJ (DSBGA-56); Manufacturer: Texas Instruments; Alternate PartNumber: BQ25970YFFT; SizeAreaWB_mm2: 16.94; SizeArea_mm2: 9.69; AEC Qualified: N; AEC Category: Q200; SizeZ_mm: 0.625; SizeY_mm: 3.4; CompType: IC; SizeX_mm: 2.85
U2 = BQ25890RTWR: I2C Controlled 5A Single Cell Charger with NVDC Power Path Management and MaxChargeTM High Voltage Adapter Support, RTW0024H (WQFN-24); Alternate PartNumber: BQ25890RTWT; Manufacturer: Texas Instruments; SymbolCreator: Altium; SizeArea_mm2: 16; SizeAreaWB_mm2: 25; SizeX_mm: 4; SizeZ_mm: 0.8; CompType: IC; U/M: EA

## Sheet PWR881E2_EVM_Hardware.SchDoc
size 431 x 279 mm; Date: Not shown in title block; ApprovedBy: Not shown in title block; CheckedBy: Not shown in title block; Author: Not shown in title block; CompanyName: Not shown in title block; Engineer: Not shown in title block; Organization: Not shown in title block; Address1: Not shown in title block; Address2: Not shown in title block; Address3: Not shown in title block; Address4: Not shown in title block; DocumentNumber: 1; Revision: Use project parameter SCH_Rev; SheetNumber: 4; SheetTotal: 4; PageSetup: Record=PageOptions¦CenterHorizontal=True¦CenterVertical=True¦PrintScale=1.00¦XCorrection=1.00¦YCorrection=1.00¦PrintKind=0¦BorderSize=5000000¦LeftOffset=0¦BottomOffset=0¦Orientation=2¦PaperLength=1000¦PaperWidth=1000¦Scale=100¦PaperSource=15¦PrintQuality=600¦MediaType=1¦DitherType=10¦PaperKind=Letter¦PrintScaleMode=1
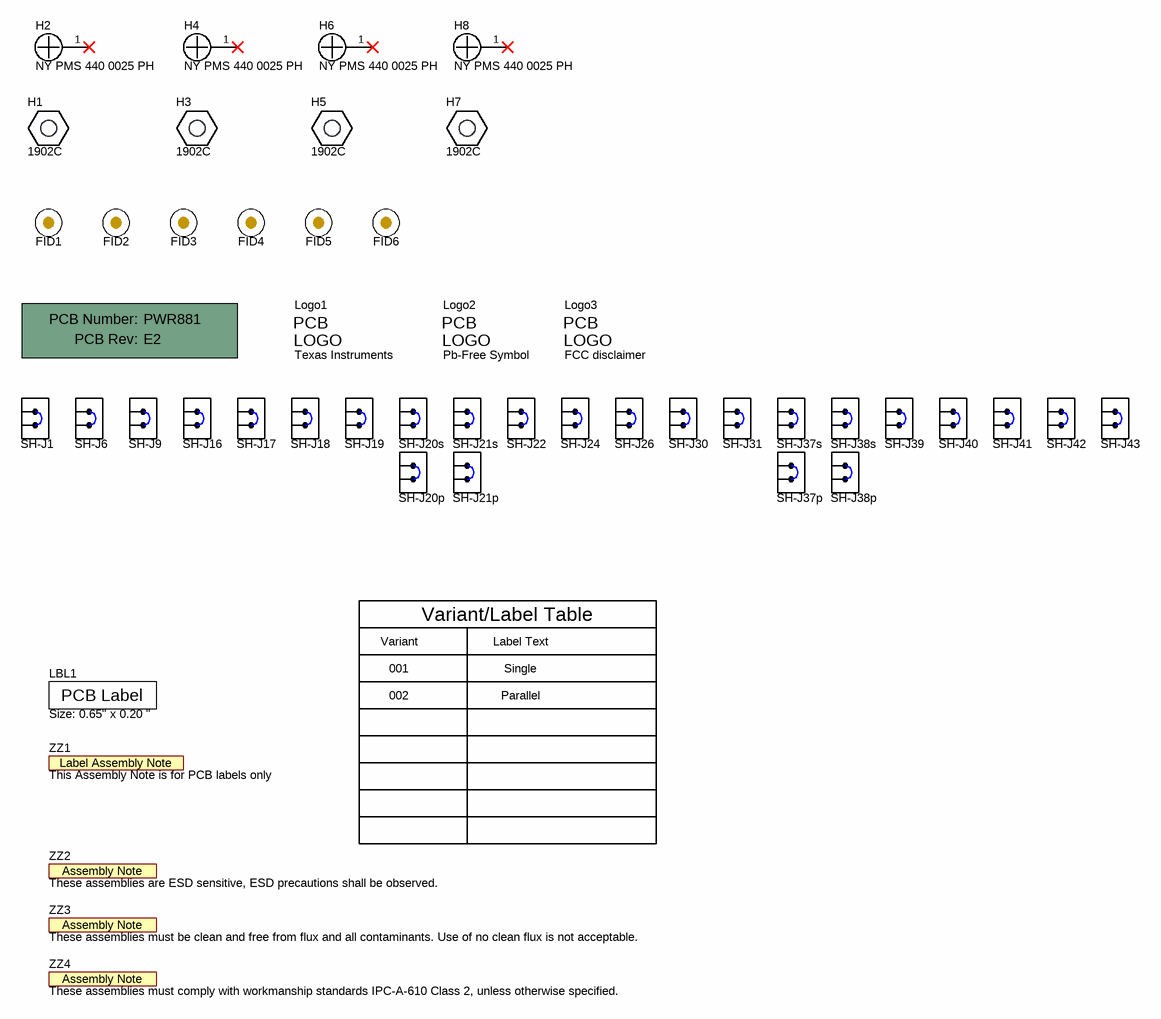
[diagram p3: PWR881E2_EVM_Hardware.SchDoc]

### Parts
!PCB1  Printed Circuit Board  (value not drawn)  (mechanical)
FID1  Fiducial  [Fiducial10-30]  (value not drawn)
FID2  Fiducial  [Fiducial10-30]  (value not drawn)
FID3  Fiducial  [Fiducial10-30]  (value not drawn)
FID4  Fiducial  [Fiducial10-30]  (value not drawn)
FID5  Fiducial  [Fiducial10-30]  (value not drawn)
FID6  Fiducial  [Fiducial10-30]  (value not drawn)
H1  1902C  [Keystone_1902C]
H2  NY PMS 440 0025 PH  [NY PMS 440 0025 PH]
H3  1902C  [Keystone_1902C]
H4  NY PMS 440 0025 PH  [NY PMS 440 0025 PH]
H5  1902C  [Keystone_1902C]
H6  NY PMS 440 0025 PH  [NY PMS 440 0025 PH]
H7  1902C  [Keystone_1902C]
H8  NY PMS 440 0025 PH  [NY PMS 440 0025 PH]
LBL1  Size: 0.65" x 0.20 "  [Label_650x200]
Logo1  Texas Instruments  [TI_Stacked_SolderMask_Small]  (no BOM)
Logo2  Pb-Free Symbol  [Pb-Free_Overlay_Small]  (no BOM)
Logo3  FCC disclaimer  [FCC_disclaimer]  (no BOM)
SH-J1  969102-0000-DA  [SNT-100-BK-G]  (value not drawn)
SH-J6  969102-0000-DA  [SNT-100-BK-G]  (value not drawn)
SH-J9  969102-0000-DA  [SNT-100-BK-G]  (value not drawn)
SH-J16  969102-0000-DA  [SNT-100-BK-G]  (value not drawn)
SH-J17  969102-0000-DA  [SNT-100-BK-G]  (value not drawn)
SH-J18  969102-0000-DA  [SNT-100-BK-G]  (value not drawn)
SH-J19  969102-0000-DA  [SNT-100-BK-G]  (value not drawn)
SH-J20p  969102-0000-DA  [SNT-100-BK-G]  (value not drawn)
SH-J20s  969102-0000-DA  [SNT-100-BK-G]  (value not drawn)
SH-J21p  969102-0000-DA  [SNT-100-BK-G]  (value not drawn)
SH-J21s  969102-0000-DA  [SNT-100-BK-G]  (value not drawn)
SH-J22  969102-0000-DA  [SNT-100-BK-G]  (value not drawn)
SH-J24  969102-0000-DA  [SNT-100-BK-G]  (value not drawn)
SH-J26  969102-0000-DA  [SNT-100-BK-G]  (value not drawn)
SH-J30  969102-0000-DA  [SNT-100-BK-G]  (value not drawn)
SH-J31  969102-0000-DA  [SNT-100-BK-G]  (value not drawn)
SH-J37p  969102-0000-DA  [SNT-100-BK-G]  (value not drawn)
SH-J37s  969102-0000-DA  [SNT-100-BK-G]  (value not drawn)
SH-J38p  969102-0000-DA  [SNT-100-BK-G]  (value not drawn)
SH-J38s  969102-0000-DA  [SNT-100-BK-G]  (value not drawn)
SH-J39  969102-0000-DA  [SNT-100-BK-G]  (value not drawn)
SH-J40  969102-0000-DA  [SNT-100-BK-G]  (value not drawn)
SH-J41  969102-0000-DA  [SNT-100-BK-G]  (value not drawn)
SH-J42  969102-0000-DA  [SNT-100-BK-G]  (value not drawn)
SH-J43  969102-0000-DA  [SNT-100-BK-G]  (value not drawn)
ZZ1  This Assembly Note is for PCB labels only  [AssemblyNoteLabel]  (no BOM)
ZZ2  These assemblies are ESD sensitive, ESD precautions shall be observed.  [AssemblyNote]  (no BOM)
ZZ3  These assemblies must be clean and free from flux and all contaminants. Use of no clean flux is not acceptable.  [AssemblyNote]  (no BOM)
ZZ4  These assemblies must comply with workmanship standards IPC-A-610 Class 2, unless otherwise specified.  [AssemblyNote]  (no BOM)

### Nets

Not connected (* = marked no-connect by the designer): H2 1*; H4 1*; H6 1*; H8 1*

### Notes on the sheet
- Variant
- Variant/Label Table
- Label Text
- 001
- 002
- Single
- Parallel

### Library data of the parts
!PCB1 = PCB: Manufacturer: Any; PartNumber: PWR881; SymbolCreator: a0412235
FID1-FID6 = Fiducial: Fiducial mark.  There is nothing to buy or mount.; SymbolCreator: codlsc
H1 H3 H5 H7 = 1902C: Standoff, Hex, 0.5"L #4-40 Nylon; Manufacturer: Keystone; CompType: Hardware; SymbolCreator: a0412235
H2 H4 H6 H8 = NY PMS 440 0025 PH: Machine Screw, Round, #4-40 x 1/4, Nylon, Philips panhead; Manufacturer: B&F Fastener Supply; CompType: Hardware; SymbolCreator: codlsc; U/M: EA
LBL1 = THT-14-423-10: Thermal Transfer Printable Labels, 0.650" W x 0.200" H - 10,000 per roll; Manufacturer: Brady; SymbolCreator: a0412235; CompType: Label
Logo1 = TI_Logo: Texas Instrument Corporate Signature; SymbolCreator: a0412235
Logo2 = Pb-Free: SymbolCreator: a0412235
Logo3 = FCC_disclaimer: SymbolCreator: a0412235
SH-J1 SH-J6 SH-J9 SH-J16-SH-J19 SH-J20p SH-J20s SH-J21p SH-J21s SH-J22 SH-J24 SH-J26 SH-J30 SH-J31 SH-J37p SH-J37s SH-J38p SH-J38s SH-J39-SH-J43 = 969102-0000-DA: Shunt, 100mil, Gold plated, Black; Manufacturer: 3M; Alternate Manufacturer: Samtec; Value: 1x2; Note: You can "mate" this to a header by matching the designator.  i.e. use SH-J3 for header J3
ZZ1 = AssemblyNoteLabel: SymbolCreator: a0412235
ZZ2-ZZ4 = AssemblyNote: SymbolCreator: codlsc

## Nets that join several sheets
3V3_SYS: PWR881E2_MCU_USB (14 pins), PWR881E2 (5 pins)
AGND: PWR881E2_MCU_USB (19 pins), PWR881E2 (22 pins)
GND: PWR881E2_MCU_USB (19 pins), PWR881E2 (97 pins)
SYS: PWR881E2_MCU_USB (C50.1 U9.2 U9.5), PWR881E2 (12 pins)
VBUS_C: PWR881E2_MCU_USB (J40.2), PWR881E2 (16 pins)
VBUS_CHG: PWR881E2_MCU_USB (U4.A2), PWR881E2 (15 pins)
CC1_SCH: PWR881E2_MCU_USB (C60.1 R70.2 U4.C1 U6.2), PWR881E2 (J23.A5)
CC2_SCH: PWR881E2_MCU_USB (C59.1 R69.2 U4.A1 U6.1), PWR881E2 (J23.B5)
CE_SCHG: PWR881E2_MCU_USB (J44.1 U5.15), PWR881E2 (R10.1)
DN_C: PWR881E2_MCU_USB (U7.7), PWR881E2 (J23.A7 J23.B7)
DN_SCHG: PWR881E2_MCU_USB (U7.2), PWR881E2 (U2.3)
DP_C: PWR881E2_MCU_USB (U7.8), PWR881E2 (J23.A6 J23.B6)
DP_SCHG: PWR881E2_MCU_USB (U7.1), PWR881E2 (U2.2)
DSEL_SCHG: PWR881E2_MCU_USB (R44.2 U5.30), PWR881E2 (U2.24)
INT_M: PWR881E2_MCU_USB (J44.4 U5.32), PWR881E2 (R1.1 TP1.1 U1.C7)
INT_S: PWR881E2_MCU_USB (J44.3 U5.31), PWR881E2 (R26.1 TP25.1 U3.C7)
INT_SCHG: PWR881E2_MCU_USB (J44.2 U5.29), PWR881E2 (R6.1 TP9.1 U2.7)
OTG_SCHG: PWR881E2_MCU_USB (U5.16), PWR881E2 (J2.1 R4.1 U2.8)
QON_SCHG: PWR881E2_MCU_USB (U5.17), PWR881E2 (U2.12)
SCL: PWR881E2_MCU_USB (R58.2 R60.1 U4.B3), PWR881E2 (U1.F7 U2.5 U3.F7)
SDA: PWR881E2_MCU_USB (R57.2 R59.1 U4.C3), PWR881E2 (U1.G7 U2.6 U3.G7)

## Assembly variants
001: not fitted C53 C54 C55 C56 C57 C58 FID1 FID2 FID3 FID4 FID5 FID6 R12 R20 R24 SH-J9 SH-J20p SH-J21p SH-J37p SH-J38p SH-J39 U1
002: not fitted C53 C54 C55 C56 C57 C58 FID1 FID2 FID3 FID4 FID5 FID6 R24 SH-J6 SH-J20s SH-J21s SH-J37s SH-J38s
